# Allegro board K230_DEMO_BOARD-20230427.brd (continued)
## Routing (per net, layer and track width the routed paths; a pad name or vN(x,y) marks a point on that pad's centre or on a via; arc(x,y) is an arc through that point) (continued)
GND_SIGNAL: length 116.1
  TOP w0.254: U1.G8 U1.G7 v2(31.17,82.61)
  TOP w0.305: v1(64.77,133.22) TVS14.2 65.53,133.99 C156.2 ; TVS13.2 v1(62.99,136.27)
  TOP w0.381: C155.2 v1(61.34,133.48) ; v1(60.71,131.95) v1(56.45,127.7) v1(48.64,119.89) 48.64,108.08 v1(48.51,107.95) v1(44.07,103.5) v1(37.34,96.77) 31.11,90.55 v3(31.11,90.17) ; FB1.1 v1(60.33,134.75) ; J7.2 v1(74.4,130.66) ; C158.1 v1(65.91,131.32) ; v1(62.48,123.19) v1(56.52,123.19) 55.88,123.19 51.21,118.52 v1(51.21,114.83) 51.21,106.96 v1(49.66,105.41) v1(41.74,97.5) 35.2,90.96 35.2,90.07 v3(34.23,89.09) ; 74.3,118.24 v1(74.3,117.35) ; C160.1 v1(69.49,120.13)
  BOTTOM w0.254: C14.2 31.37,82.8 v2(31.17,82.61) ; 33.91,87.38 33.91,86.23
  BOTTOM w0.305: C238.2 41.71,97.54 v1(41.74,97.5)
  vias: v1(61.47,138.94) v1(64.26,138.94)
VDD_1V8: length 63.1
  TOP w0.203: v1(57.68,119.88) 58.11,119.45 U25.2 ; v2(42.52,111.23) 42.66,111.09 U30.C6 ; U30.P5 43.16,116.48 v2(42.93,116.71) ; v2(44.32,116.71) 44.32,116.44 U30.P3 U30.N4 U30.M4
  TOP w0.254: U1.R13 25.65,78.38 v2(25.33,78.06) ; U1.H6 v2(30.53,82.61) ; U1.R15 v2(25.33,77.41) ; U1.R11 v2(25.33,79.36) ; U1.F13 v2(31.17,78.06) ; v2(32.47,79.36) 32.15,79.68 U1.E11
  TOP w0.305: v1(57.3,115.06) R209.1 ; R143.1 14.61,44.07 ; R153.1 v1(40.64,16.26) ; R168.2 v1(29.21,26.04) ; v1(57.68,119.88) C207.1 ; R36.1 v1(31.75,26.04)
  TOP w0.381: R158.1 14.61,18.54 ; 72.26,38.73 v1(73.03,38.73) ; TP2.1 v1(13.84,15.88) ; R238.1 R239.1 v1(44.58,124.46) ; v1(51.31,82.93) 51.27,82.97 Y4.4 ; v1(45.72,124.46) R240.1 R241.1 ; R206.1 v1(7.11,40.64) ; R198.1 v1(7.11,48.26) ; J12.1 4.57,53.21 C206.2 ; R148.2 v1(20.7,26.16) ; R207.1 v1(7.11,38.1) ; 72.26,41.27 v1(73.03,41.27) ; R200.1 v1(7.11,43.18) ; R199.1 v1(7.11,45.72) ; J9.1 v1(32.7,119.89) ; R197.1 v1(7.11,50.8)
  ART06 w0.254: v2(31.17,78.06) v2(32.47,79.36)
  BOTTOM w0.254: v2(42.93,116.71) 43.18,116.46 C257.1 R49.2 v2(44.32,116.71) ; C258.1 41.15,111 R59.2 ; C258.1 42.29,111 v2(42.52,111.23) ; C258.1 42.04,109.98 C256.1
  BOTTOM w0.305: C10.1 v1(51.31,82.93) 48.64,82.93 47.24,81.53 40.77,81.53 39.75,80.52 38.99,80.52 38.99,79.5 ; v1(32.7,119.89) 32.7,120.21 C242.2 ; R236.1 R237.1 v1(5.71,82.51) ; R48.2 C259.1 v1(36.7,109.73)
  BOTTOM w0.381: v3(41.4,128.14) R234.1 R235.1
  vias: v1(15.24,46.99) v1(15.24,45.97) v1(15.24,44.07) v1(15.24,21.46) v1(15.24,20.45) v1(15.24,18.67) v1(15.24,17.65) v1(20.19,17.65) v1(20.19,16.64) v1(21.21,17.65) v1(21.21,16.64) v1(22.23,17.65) v1(22.23,16.64) v1(22.61,26.92) v1(22.61,25.91) v1(22.99,29.97) v1(22.99,28.96) v1(23.24,17.65) v1(23.24,16.64) v1(27.94,29.72) v1(27.94,28.83) v1(27.94,26.92) v1(27.94,25.91) v1(46.48,113.79) v1(47.37,113.79)
VDD_3V3: length 75.9
  TOP w0.203: U16.2 44.88,121.23 v1(44.32,121.79) ; U30.F5 42.82,112.28 v2(42.79,112.25) 42.66,112.12 U30.E6 ; v1(58.82,119.88) 58.51,119.57 U25.1 ; U30.K9 v2(41.16,113.8) 41.14,113.78 U30.J10
  TOP w0.254: U1.E10 v2(32.47,80.66) ; U1.M7 v2(27.28,82.61)
  TOP w0.305: J3.57 46.76,128.93 ; C272.2 v1(44.32,121.79) ; R156.1 v1(40.64,6.73) ; R139.1 35.94,27.56 ; J4.6 6.86,91.41 v1(6.6,91.15) 6.85,90.91 J4.5 ; v1(58.82,119.88) C208.2 ; J3.59 47.26,128.92
  TOP w0.381: v1(62.74,117.22) R243.1 R242.1 ; R19.1 19.3,8.89 ; R265.1 v1(59.69,23.68) ; R222.2 v1(15.62,10.79) ; v1(71.75,87) 67.06,87 66.86,87.19 U4.4 ; J9.16 v1(32.7,105.79) ; TP5.1 v1(13.59,9.91)
  BOTTOM w0.254: C18.1 41.15,113.82 v2(41.16,113.8) ; v2(32.47,80.66) 32.59,80.77 33.31,80.77
  BOTTOM w0.305: v2(42.79,112.25) 42.8,112.27 C22.1 C19.1 ; C81.1 C30.1 27.18,85.09 ; 35.81,80.14 C83.1 35.81,79.25 36.63,78.44 39.19,78.44 39.85,79.1 49.38,79.1 53.72,83.44 53.72,88.39 54.74,89.41 54.74,90.55 v1(58.42,94.23) ; R23.2 v1(43.43,117.47)
  BOTTOM w0.381: v1(32.7,105.79) 32.7,105.35 C260.1 ; R188.1 v1(70.99,85.09) ; R162.1 v1(70.99,87.63) ; R194.1 v1(70.99,83.19) R189.1 ; R245.2 v1(70.99,86.36) ; R191.1 v1(70.99,90.17) ; R190.1 v1(70.99,81.92) ; R193.1 v1(70.99,88.9)
  vias: v1(7.24,26.92) v1(7.24,25.65) v1(9.02,26.92) v1(9.02,25.65) v1(10.16,26.92) v1(10.16,25.65) v1(15.37,33.91) v1(15.37,32.89) v1(19.68,7.62) v1(19.68,6.48) v1(20.7,7.62) v1(20.7,6.48) v1(22.23,7.62) v1(22.23,6.48) v1(23.24,7.62) v1(23.24,6.48) v1(36.07,26.92) v1(36.07,25.91) v1(37.08,26.92) v1(37.08,25.91) v1(47.37,128.78) v1(48.39,128.78) v1(49.4,128.78) v1(50.55,128.78) v1(58.42,95.38) v1(59.82,98.17) v1(60.71,98.17) v2(38.1,114.43) v2(38.1,113.79)
VDD_5V: length 10.6
  TOP w0.254: U18.2 57.55,73.17
  TOP w0.305: U17.3 36.57,19.93 ; U20.3 51.05,49.15 ; R246.1 v1(19.56,26.16) ; U11.4 29.46,29.47 v1(29.59,29.34) 30.48,28.45 C164.1 ; U21.3 36.57,10.41 ; R151.1 v1(47.24,45.09)
  TOP w0.381: R172.1 56.9,79.63 v1(56.9,80.01) ; R186.1 42.93,28.83 ; R137.2 64.14,27.3
  vias: v1(37.08,20.83) v1(37.08,19.81) v1(37.08,11.3) v1(37.08,10.29) v1(38.35,19.81) v1(38.35,10.29) v1(39.62,19.81) v1(39.62,10.29) v1(50.93,48.64) v1(50.93,47.37) v1(50.93,46.1) v1(52.07,48.64) v1(53.98,25.53) v1(55.12,19.56) v1(55.12,18.29) v1(55.24,25.53) v1(55.24,24.26) v1(55.24,22.99) v1(55.24,21.72) v1(56.39,19.56) v1(56.39,18.29) v1(57.28,71.63) v1(57.28,70.36) v1(57.28,69.09) v1(57.28,67.82) v1(57.66,19.56) v1(57.66,18.29) v1(59.05,19.56) v1(59.05,18.29) v1(61.59,19.56) v1(61.59,18.29) v1(62.87,19.56) v1(62.87,18.29) v1(63.5,49.78) v1(64.14,19.56) v1(64.14,18.29) v1(64.77,49.78) v1(64.77,48.51) v1(64.77,47.24) v1(65.41,19.56) v1(65.41,18.29) v3(43.56,30.73) v3(43.56,29.72) v3(43.81,45.97) v3(43.81,44.96)
VDD_5V_O: length 24.5
  TOP w0.305: v1(57.53,85.47) 54.36,88.65 R43.2 R39.2 ; J4.4 8.88,90.41 ; J3.60 47.26,135.75 47.24,135.76 ; J3.58 46.76,135.75 ; J3.56 46.26,135.75 ; J4.3 8.88,89.91
  TOP w0.381: v1(66.55,67.5) U3.5 ; v1(66.55,57.34) U6.5
  BOTTOM w0.381: C16.2 66.61,67.56 v1(66.55,67.5) 65.85,67.5 ; 65.72,57.34 v1(66.55,57.34) 66.61,57.4 C20.2
  vias: v1(9.02,90.17) v1(9.02,89.15) v1(9.91,89.66) v1(40.64,137.41) v1(40.64,136.14) v1(41.91,137.41) v1(41.91,136.14) v1(62.48,31.24) v1(62.48,30.23) v1(64.52,31.24) v1(64.52,30.23) v1(67.69,31.24) v1(67.69,30.23)
VDD_CORE_0V8: length 92.9
  TOP w0.254: U1.K11 v2(29.22,80.01) ; v2(29.22,80.66) 28.9,80.98 U1.K9 ; U1.P9 v2(26.63,81.31) U1.N9 ; U1.M11 v2(27.93,79.36) ; U1.G10 v2(31.17,80.01) ; v2(30.53,80.66) 30.85,80.98 U1.G9 ; U1.F12 v2(31.17,78.71) ; U1.L11 v2(28.57,80.01) ; U1.L9 v2(27.93,81.31) U1.M9 ; U1.N11 v2(26.63,79.36) ; U1.P13 v2(25.98,78.71) ; U1.P11 v2(25.98,79.36)
  TOP w0.305: 41.4,78.36 41.4,78.11 41.78,77.72 41.78,76.96
  ART06 w0.305: v1(43.24,8.26) 43.24,28.01 40.26,30.99 40.26,47.24 47.5,54.48 47.5,60.96 v1(48.64,62.1)
  BOTTOM w0.254: C44.1 38.23,73.79 v2(37.72,73.28) ; C39.1 27.05,81.79 26.63,81.36 v2(26.63,81.31) ; C43.1 C36.1 C37.1 37.08,76.53 v2(36.5,77.11) ; v2(26.63,79.36) 26.48,79.5 C47.1 ; v2(39.62,81.41) 39.5,81.53 38.99,81.53 38.99,83.31 ; C38.1 28.32,81.79 27.93,81.39 v2(27.93,81.31)
  BOTTOM w0.305: v1(43.24,8.26) 31.75,8.26 27.94,4.45
  vias: v1(46.61,63.25) v1(46.61,62.1) v1(47.62,63.25) v1(48.64,64.64) v1(48.64,63.25) v1(50.04,64.64) v1(50.04,63.63) v1(51.44,64.64) v1(51.44,63.63) v1(51.44,62.61) v1(51.44,61.59) v2(40.39,80.37) v2(40.39,79.58) v2(40.39,78.61)
VDD_CORE_SY: length 80.5
  TOP w0.305: 47.62,57.15 47.62,48.9 C190.2 R174.2
  ART06 w0.305: v1(44.63,8.26) 44.63,27.76 41.53,30.86 41.53,47.62 48.13,54.23 48.13,58.29 v1(48.64,58.8)
  BOTTOM w0.305: v1(44.63,8.26) 43.87,7.49 33.53,7.49 30.48,4.45
VDD_CPU_0V8: length 41.1
  TOP w0.254: U1.J12 v2(29.87,78.71) ; U1.G12 v2(30.52,78.71) U1.H12
  ART06 w0.381: v1(50.8,37.47) 47.5,34.16 47.5,4.57 45.97,3.05 44.32,3.05 43.18,1.91
  vias: v1(51.82,40.77) v1(51.82,37.47) v1(52.83,40.77) v1(52.83,39.75) v1(52.83,38.48) v1(52.83,37.47) v1(53.85,40.77) v1(53.85,39.75) v1(54.86,40.77) v1(54.86,39.75) v1(56.01,40.77) v1(56.01,39.75) v1(56.01,38.48) v3(44.32,73.03) v3(45.09,73.03) v3(45.09,72.26)
VDD_CPU_TI: length 39
  TOP w0.254: 50.67,33.37 50.67,28.96 51.19,28.44 U28.8
  ART06 w0.381: v1(50.67,33.4) 50.04,32.77 50.04,20.57 48.13,18.67 48.13,4.32 45.72,1.91
VDD_IO1V8_SY: length 31
  TOP w0.305: R149.2 C170.2 28.96,17.02
  ART06 w0.254: v1(27.94,17.02) 27.94,13.72 36.83,4.83 36.83,3.68 37.34,3.17 39.37,3.17 40.64,1.91
VDD_IO3V3_SY: length 13.5
  TOP w0.305: 24.96,7.68 24.96,6.54 22.86,4.45 ; 28.96,7.49 C196.2 R169.2
VDD_KPU_0V8: length 95.8
  TOP w0.254: U1.H10 v2(29.87,80.66) U1.J10 ; U1.J9 v2(29.87,81.31) U1.H9 ; U1.H8 v2(29.87,81.96) U1.J8
  TOP w0.305: v1(68.58,13.08) 67.94,12.45 67.94,7.37 66.67,6.1 39.75,6.1 38.1,4.45
  ART06 w0.305: v1(68.58,13.08) 67.06,14.61 67.06,42.8 67.98,43.73 67.98,52.16 65.8,54.34 65.8,57.26 62.23,60.83 61.84,60.83 60.96,61.71 v1(60.96,62.14)
  BOTTOM w0.254: C53.1 C54.1 C55.1 v2(37.21,86.87)
  vias: v1(50.8,89.41) v1(52.58,89.41) v1(53.72,89.41) v1(55.63,89.41) v1(57.53,89.28) v1(57.53,88.01) v1(59.31,89.28) v1(59.31,88.01) v1(59.94,65.19) v1(59.94,64.17) v1(59.94,63.16) v1(60.33,89.28) v1(60.33,88.01) v1(60.96,65.19) v1(60.96,64.17) v1(60.96,63.16) v1(61.34,89.28) v1(61.34,88.01) v1(62.23,65.19) v1(62.23,64.17) v1(62.23,63.16) v1(62.23,62.14) v1(64.39,65.15) v2(41.02,84.98) v2(41.02,83.82)
VDD_KPU_TI: length 93.3
  TOP w0.254: U27.8 61.35,51.94 60.83,52.45 60.83,57.4
  TOP w0.305: v1(68.58,12.06) 68.58,7.24 66.93,5.59 41.78,5.59 40.64,4.45
  ART06 w0.305: v1(68.58,12.06) 68.58,12.19 66.55,14.22 66.55,43.18 67.5,44.13 67.5,51.93 66,53.43 61.14,53.43 60.83,53.73 v1(60.83,58.55)
3D_CTRL_IN: length 83.8
  TOP w0.127: R83.1 v1(6.22,77.34) ; J3.49 44.76,131.39 44.32,131.83 v3(43.94,131.83)
  ART06 w0.127: v3(43.94,131.83) 43.69,132.08 42.74,132.08 40.32,129.67 33.27,129.67 21.21,117.6 21.21,88.77 19.3,86.87 14.73,86.87 13.21,85.34 8.51,85.34 7.51,84.34 7.51,78.63 v1(6.22,77.34)
3D_CTRL_OUT1: length 89.3
  TOP w0.127: v3(42.82,131.6) 43,131.42 43.97,131.42 44.26,131.13 J3.47 ; R85.1 v1(6.22,70.48)
  ART06 w0.127: v1(6.22,70.48) 7.79,72.05 7.79,84.11 8.66,84.99 13.46,84.99 14.9,86.42 19.49,86.42 21.59,88.52 21.59,117.47 33.4,129.29 40.51,129.29 v3(42.82,131.6)
3D_CTRL_OUT2: length 89.5
  TOP w0.127: v1(2.41,80.14) 4.7,80.14 6.35,78.49 R87.1 ; v3(43.76,132.59) J3.46
  ART06 w0.127: v3(43.76,132.59) 43.25,133.1 32.44,133.1 18.03,118.69 18.03,92.96 15.49,90.42 12.05,90.42 9.89,88.27 6.22,88.27 4.45,86.49 3.56,86.49 1.02,83.95 1.02,81.53 v1(2.41,80.14)
ADC_0: length 58.1
  TOP w0.127: v1(53.72,103.89) 50.16,100.33 50.16,93.47 49.4,92.71 49.4,91.95 R25.1 ; R51.1 47.62,124.97 v1(47.62,123.32)
  ART06 w0.127: v1(53.72,103.89) 52.7,103.89 50.04,106.55 50.04,120.9 v1(47.62,123.32)
  BOTTOM w0.127: v1(47.62,123.32) 47.62,124.71 49.91,127 49.91,133.22 46.48,136.65 45.59,136.65 J15.1
ADC_1: length 51.8
  TOP w0.127: v1(52.66,104.73) 49.4,101.47 49.4,94.23 R26.1 ; v1(49.91,123.44) 49.91,124.97 R52.1
  ART06 w0.127: v1(52.66,104.73) 50.55,106.85 50.55,122.81 v1(49.91,123.44)
  BOTTOM w0.127: v1(49.91,123.44) 49.91,124.97 51.18,126.24 51.18,133.6 J15.2
ADC_2: length 59.7
  TOP w0.127: R27.1 49.78,91.19 49.78,92.33 50.55,93.09 50.55,99.82 54.23,103.5 54.23,106.3 53.09,107.44 v1(52.7,107.44) ; J3.52 45.26,132.62 46.3,131.57 v1(47.88,131.57) 49.53,133.22 J15.3
  ART06 w0.127: v1(47.88,131.57) 47.88,128.52 53.72,122.68 53.72,115.95 52.07,114.3 52.07,108.08 v1(52.7,107.44)
ADC_3: length 46.7
  TOP w0.127: R28.1 48.39,101.73 v1(52.66,106)
  ART06 w0.127: v1(52.66,106) 52.66,106.51 53.59,107.44 53.59,114.33 55.5,116.24 55.5,134.37 J15.4
ADC_4: length 49.8
  TOP w0.127: v1(53.68,104.86) 49.78,100.97 49.78,93.85 49.02,93.09 49.02,92.71 R29.1
  ART06 w0.127: J15.5 55.88,136.53 55.88,116.08 53.98,114.17 53.98,107.19 53.17,106.38 53.17,105.37 v1(53.68,104.86)
ADC_5: length 63.8
  TOP w0.127: 71.75,118.24 v1(71.75,117.35) ; v1(53.68,106) 53.04,105.37 52.54,105.37 49.02,101.85 49.02,95 R30.1
  ART06 w0.127: v1(71.75,117.35) 64.01,117.35 62.74,116.08 57.66,116.08 57.02,116.71 ; v1(53.68,106) 54.36,106.68 54.36,114.05 57.02,116.71 ; J15.6 57.15,136.78 57.02,136.65 57.02,116.71
BOOT0: length 77.2
  TOP w0.127: SW1.1 64.77,43.18 65.02,43.43 v1(70.87,43.43) TVS4.1 70.87,41.66 R18.1 ; U1.C8 v2(33.77,81.96)
  ART06 w0.127: v2(33.77,81.96) 36.75,81.96 36.96,82.17 41.27,82.17 42.29,81.15 47.5,81.15 50.55,78.11 52.45,78.11 55.5,75.06 55.5,71.63 56.13,70.99 58.93,70.99 63.82,66.1 63.82,62.55 65.41,60.96 68.83,60.96 70.1,59.69 70.1,56.9 71.5,55.5 71.5,44.07 v1(70.87,43.43)
BOOT1: length 80.9
  TOP w0.127: U1.C9 33.13,81.31 v2(33.12,81.31) ; SW1.2 62.23,40.51 62.74,40.01 v1(69.34,40.01) TVS5.1 70.87,39.12 R20.1
  ART06 w0.127: v2(33.12,81.31) 33.65,80.78 40.75,80.78 42.04,79.5 47.88,79.5 50.67,76.71 52.96,76.71 54.74,74.93 54.74,70.61 56.9,68.45 60.45,68.45 63.12,65.79 63.12,62.23 65.28,60.07 66.07,60.07 68.45,57.68 68.45,53.98 70.61,51.82 70.61,44.58 69.34,43.31 v1(69.34,40.01)
CC1: length 6.6
  TOP w0.127: J2.B5 73.45,15.7 73.91,15.24 v1(73.91,13.46) 73.91,13.08 73.53,12.7 J2.A5
  BOTTOM w0.127: R9.1 v1(73.91,13.46)
CC_T: length 13
  TOP w0.127: R195.1 68.45,109.22 69.53,108.15 69.53,106.5 70.11,105.91 J6.B5 73.29,105.91 74.17,105.03 74.17,103.76 73.32,102.91 J6.A5
DDR_1V8: length 50.1
  TOP w0.254: v2(23.05,51.34) 23.38,51.01 U5.A4 ; v2(23.7,52.94) 23.7,52.87 U5.A6 ; v2(23.7,49.74) 23.7,49.81 U5.A3 ; U5.U10 v2(34.42,55.74) ; v2(34.1,52.14) 34.1,52.22 U5.U6 ; U5.A10 v2(22.61,55.74) ; v2(34.1,49.74) 34.1,49.81 U5.U3 ; v2(34.1,51.34) 34.1,51.41 U5.U5 ; U5.U4 34.1,50.61 v2(34.1,50.54) ; U5.A5 23.38,51.81 v2(23.05,52.14)
  ART06 w0.305: J10.3 41.91,5.71 41.91,24 35.94,29.97 35.94,40.77 v1(35.81,40.89)
  BOTTOM w0.254: C121.1 23.47,52.7 v2(23.7,52.94) 23.7,54.65 v2(22.61,55.74) ; v2(23.7,49.74) 23.09,49.74
  vias: v1(21.21,49.78) v1(21.21,48.77) v1(34.67,42.04) v1(34.67,40.89) v1(35.81,42.04) v1(36.96,42.04) v1(36.96,40.89)
DDR_1V8_TI: length 34.3
  TOP w0.305: R138.2 35.94,35.18
  ART06 w0.305: J10.1 42.42,7.75 42.42,24.26 37.34,29.34 37.34,33.66 v1(36.7,34.29)
DDR_CORE_0V8: length 57
  TOP w0.254: U1.M13 v2(27.28,78.06) ; U1.L13 v2(28.58,78.71) U1.K13 ; U1.N13 v2(26.63,78.06)
  ART06 w0.254: v1(18.03,53.09) 16.51,53.09 11.94,48.51 11.94,38.61 11.43,38.1 11.43,8.26 15.24,4.45
  BOTTOM w0.254: C65.1 21.27,76.96 v2(21.06,76.75) 21.06,76.49 21.46,76.09 C66.1
  vias: v1(18.03,55.12) v1(18.03,54.08) v2(22.35,69.72) v2(22.35,68.95)
DDR_CORE_TI: length 50.2
  TOP w0.305: R177.1 14.61,51.44
  ART06 w0.305: 17.78,4.45 11.94,10.29 11.94,37.72 13.21,38.99 13.21,48.39 v1(14.99,50.16)
DDR_VAA_1V8: length 1.9
  TOP w0.254: U1.K15 v2(29.22,76.76)
  BOTTOM w0.254: C77.1 29.28,76.71 v2(29.22,76.76) ; C76.1 32.13,73.85 v2(31.82,74.16)
  vias: v1(38.35,42.04) v1(38.35,40.89) v1(39.5,42.04) v1(39.5,40.89) v1(40.89,42.04) v1(40.89,41.02)
DDR_VDD2_1V2: length 101.8
  TOP w0.203: v2(25.65,58.54) 26.06,58.13 26.06,57.43 25.98,57.34 U5.E12
  TOP w0.254: v2(32.15,50.54) 31.82,50.86 U5.P4 ; U5.E8 25.65,54.46 v2(25.65,54.54) ; v2(31.5,57.74) 31.5,57.67 U5.N12 ; U5.A11 v2(22.61,56.54) ; v2(27.6,51.34) 27.28,51.66 U5.G5 ; v2(26.95,48.94) 26.95,49.01 U5.G2 ; U5.A8 22.96,53.72 v2(22.48,53.72) ; U5.M2 30.85,49.01 v2(30.85,48.94) ; U1.L14 v2(27.93,77.41) ; v2(28.25,53.74) 28.25,53.81 U5.H8 ; U5.L12 29.87,57.42 v2(29.55,57.74) ; U5.U11 v2(34.38,56.54) ; v2(30.2,51.34) 30.2,51.41 U5.L5 ; U1.J14 v2(29.22,77.41) ; v2(27.6,49.74) 27.6,49.81 U5.H3 ; U5.H11 27.93,56.47 v2(28.25,56.14) ; U5.D5 25.33,51.81 v2(25,52.14) ; U5.U9 v2(34.42,54.94) ; U5.K12 29.22,57.27 v2(29.55,56.94) ; U1.H14 v2(29.87,77.41) ; v2(29.55,51.34) 29.55,51.41 U5.K5 ; v2(25,58.54) 24.51,58.05 24.51,57.5 U5.C12 ; U5.L2 30.2,49.01 v2(30.2,48.94) ; U5.U8 34.04,53.88 v2(34.04,53.34) ; U5.G12 27.28,57.42 v2(27.6,57.74) 27.93,57.42 U5.H12 ; U5.H9 27.6,54.62 v2(27.6,54.54) ; v2(28.25,52.14) 27.93,51.81 U5.H5 ; U5.J6 28.57,52.61 v2(28.9,52.94) ; U5.D4 25.33,51.01 v2(25,51.34) ; v2(32.8,57.74) 32.8,57.67 U5.R12 ; v2(27.28,77.41) U1.M14 ; U5.J5 28.57,51.81 v2(28.9,52.14) ; U5.A9 v2(22.61,54.94) ; v2(30.1,61.85) C91.2 R66.2 ; v2(30.85,53.74) 31.17,54.07 U5.N8 ; U5.J10 28.57,55.67 v2(28.25,55.34) ; v2(27.6,52.14) 27.6,52.22 U5.H6 ; v2(26.3,48.94) 26.3,49.01 U5.F2 ; v2(29.55,56.14) 29.22,56.47 U5.K11 ; v2(25.65,52.94) 25.65,52.86 U5.D6 ; U5.J9 28.25,54.62 v2(28.25,54.54) ; U5.P5 31.82,51.66 v2(32.15,51.34) ; v2(32.15,52.94) 32.15,52.86 U5.P6 ; v2(28.9,53.74) 29.22,54.07 U5.K8 ; v2(26.63,77.41) U1.N14 ; v2(29.55,52.14) 29.55,52.22 U5.K6
  TOP w0.381: C264.2 R68.1 28.96,43.81 v1(29.46,43.31) ; R144.1 v1(16.76,30.99)
  ART06 w0.254: 27.94,1.91 26.67,3.17 26.67,5.97 17.4,15.24 17.4,30.35 v1(16.76,30.99) 17.4,31.62 17.4,39.88 v1(19.81,42.29)
  BOTTOM w0.254: v2(31.18,74.16) 30.99,73.97 C62.2 R57.1 C71.1 ; C72.1 27.94,75.45 v2(27.93,75.46) ; C74.1 28.14,77.19 v2(27.93,77.41)
  BOTTOM w0.381: R131.1 R84.1 ; R84.1 v1(36.32,43.31) ; R84.1 R133.1 ; v1(21.46,43.31) R258.1 R260.1 ; v1(28.32,43.31) R72.1 R71.1 ; R80.1 v3(36.96,53.09) ; R141.1 R76.1 v1(26.04,43.31) ; v1(23.75,43.31) R256.1 R254.1 ; R74.1 v1(31.75,43.31) ; R129.1 R88.1 v1(34.04,43.31)
  vias: v1(18.8,47.88) v1(18.8,46.86) v1(19.81,41.02) v1(21.08,42.29) v1(21.08,41.02) v1(22.35,42.29) v1(23.62,42.29) v1(24.89,42.29) v1(26.16,42.29) v1(27.43,42.29) v1(28.7,42.29) v1(29.97,42.29) v1(31.24,42.29) v1(32.51,42.29) v3(32.84,68.96) v3(34.04,68.97)
DDR_VDDQ_TI: length 39.7
  TOP w0.381: R38.1 28.38,36.58
  ART06 w0.305: v1(27.94,34.54) 26.67,33.27 26.67,13.59 34.16,6.1 34.16,3.68 33.66,3.17 31.75,3.17 30.48,1.91
DDR_VREF: length 6.6
  TOP w0.203: U1.K17 v2(29.22,75.46)
  BOTTOM w0.254: R58.1 R57.2 30.24,72.28 30.24,73.27 C62.1 C261.2 C262.1 29.33,75.56 v2(29.22,75.46)
DEBUG_DM: length 10.6
  TOP w0.114: J6.A7 71.58,104.41 ; 71.58,104.41 71.34,104.17 71.34,103.72 71.65,103.41 J6.B7 ; 71.58,104.41 71.42,104.57 69.83,104.57 66.59,107.81 66.04,107.81 65.96,107.73 U26.7
DEBUG_DP: length 11.5
  TOP w0.114: U26.8 65.96,108.23 66.04,108.15 66.73,108.15 69.97,104.91 J6.B6 73.38,104.91 73.5,104.8 73.5,104.02 73.38,103.91 J6.A6
DL_M_CLK2: length 77.1
  TOP w0.127: v1(6.35,79.63) R116.2 ; v3(40.25,131.57) J3.31
  ART06 w0.127: v1(6.35,79.63) 6.72,80 6.72,84.73 8.14,86.16 10.68,86.16 12.66,88.14 19.18,88.14 20.32,89.28 20.32,117.98 32.89,130.56 39.24,130.56 v3(40.25,131.57)
DL_M_CLK3: length 94.5
  TOP w0.127: R118.2 6.5,69.34 4.85,70.99 3.56,70.99 3.17,71.37 3.17,78.23 1.65,79.76 v1(1.65,82.3) ; J3.35 41.26,131.59 v3(40.26,132.59)
  ART06 w0.127: v3(40.26,132.59) 39.88,132.59 39.37,132.08 32.14,132.08 18.67,118.61 18.67,92.84 15.75,89.92 12.27,89.92 10.11,87.76 6.48,87.76 4.7,85.98 3.81,85.98 1.65,83.82 v1(1.65,82.3)
DP_M_CLK1: length 83.1
  TOP w0.127: R89.1 6.22,76.2 5.59,76.83 5.59,77.98 v1(4.45,79.12) ; J3.26 v3(38.75,131.57)
  ART06 w0.127: v3(38.75,131.57) 32.35,131.57 19.3,118.53 19.3,89.92 18.54,89.15 12.23,89.15 10.25,87.17 6.65,87.17 5.26,85.78 5.26,83.87 4.45,83.06 v1(4.45,79.12)
DP_RST: length 5.8
  TOP w0.127: v3(43.31,135.12) 43.26,135.06 J3.44
  BOTTOM w0.127: R179.1 43.31,131.43 v3(43.31,135.12)
DP_STROBE: length 6.6
  TOP w0.127: J3.50 44.76,134.8 45.08,135.12 v3(45.71,135.12)
  BOTTOM w0.127: v3(45.71,135.12) 46.48,134.35 R181.1
DP_VSYNC: length 5.9
  TOP w0.127: J3.48 v3(44.26,135.12)
  BOTTOM w0.127: R180.1 44.83,131.18 44.83,134.54 v3(44.26,135.12)
EMMC_CLK: length 44.4
  TOP w0.127: U1.A5 37.99,83.59 v2(38.35,83.95)
  BOTTOM w0.127: R50.1 38.73,110.11 42.42,106.43 43.94,106.43 49.4,100.97 49.4,91.69 47.21,89.5 47.21,86.83 45.83,85.46 44.59,85.46 44.2,85.85 43.46,85.85 42.06,84.45 38.86,84.45 v2(38.35,83.95)
EMMC_CMD: length 50.7
  TOP w0.127: v2(43.16,114.81) U30.M5 ; U1.D6 v2(33.12,83.26)
  BOTTOM w0.076: v2(33.12,83.26) 33.45,83.58 34.03,83.58
  BOTTOM w0.127: v2(43.16,114.81) 42.65,115.32 42.29,115.32 42.16,115.19 42.16,113.66 41.66,113.16 37.85,113.16 37.47,112.78 R48.1 37.97,111.89 38.1,111.76 38.1,109.98 39.12,108.97 39.12,105.28 46.5,97.9 46.5,91.86 42.14,87.5 40.51,87.5 39.5,86.49 38.35,86.49 35.45,83.58 34.03,83.58
EMMC_D0: length 50.8
  TOP w0.127: U30.A3 44.16,109.13 44.32,108.97 44.32,107.7 39.62,103 v1(39.5,103) ; U1.D5 v2(33.12,83.91)
  BOTTOM w0.076: 34.03,84.23 33.45,84.23 v2(33.12,83.91)
  BOTTOM w0.127: 34.03,84.23 35.08,84.23 38.1,87.25 39.24,87.25 41.78,89.79 41.78,90 41.29,90.49 41.29,90.7 41.44,90.85 41.65,90.85 42.14,90.36 42.35,90.36 43.18,91.19 44.45,91.19 45.72,92.46 45.72,97.41 44.32,98.81 38.86,98.81 38.73,98.93 38.73,99.31 38.86,99.44 39.75,99.44 39.88,99.57 39.88,99.82 39.7,100 38.88,100 38.73,100.15 38.73,100.36 38.88,100.51 39.86,100.51 39.98,100.64 39.98,100.86 39.83,101.02 38.88,101.02 38.73,101.17 38.73,101.38 38.88,101.53 39.88,101.53 40.01,101.65 40.01,101.98 39.88,102.11 38.88,102.11 38.73,102.26 38.73,102.85 38.88,103 v1(39.5,103)
EMMC_D1: length 50.7
  TOP w0.127: v1(39.5,103.89) 39.75,103.89 43.18,107.31 43.18,108.2 43.66,108.68 U30.A4 ; U1.C5 v2(33.77,83.91)
  BOTTOM w0.127: v2(33.77,83.91) 35.27,83.91 38.23,86.87 39.37,86.87 42.44,89.94 42.65,89.94 43.14,89.45 43.35,89.45 43.5,89.6 43.5,89.81 43.01,90.3 43.01,90.51 43.31,90.81 44.7,90.81 46.1,92.2 46.1,97.66 44.39,99.38 42.79,99.38 42.64,99.53 42.64,100.94 42.49,101.09 42.28,101.09 42.13,100.94 42.13,99.53 41.98,99.38 41.65,99.38 41.5,99.53 41.5,102.11 41.38,102.23 41.12,102.23 41,102.11 41,99.53 40.85,99.38 40.58,99.38 40.39,99.57 40.39,103 v1(39.5,103.89)
EMMC_D2: length 50.8
  TOP w0.076: 35.05,83.91 34.42,83.91 U1.B5
  TOP w0.127: v1(41.4,106.55) 41.4,107.82 42.16,108.58 42.67,108.58 43.16,109.07 U30.A5 ; 35.05,83.91 37.68,83.91 38.73,84.96 v2(39.24,84.96)
  BOTTOM w0.127: v1(41.4,106.55) 41.4,106.17 41.66,105.92 43.69,105.92 48.13,101.47 48.13,101.17 48.28,101.02 48.62,101.02 48.77,100.87 48.77,100.66 48.62,100.51 48.28,100.51 48.13,100.37 48.13,100.16 48.28,100.01 48.75,100.01 48.9,99.86 48.9,99.65 48.75,99.5 48.28,99.5 48.13,99.36 48.13,99.14 48.28,99 48.75,99 48.9,98.85 48.9,98.64 48.75,98.49 48.28,98.49 48.13,98.34 48.13,98.13 48.28,97.98 48.75,97.98 48.9,97.83 48.9,97.62 48.75,97.47 48.28,97.47 48.13,97.32 48.13,97.11 48.28,96.96 48.75,96.96 48.9,96.82 48.9,96.6 48.75,96.46 48.28,96.46 48.13,96.31 48.13,96.1 48.28,95.95 48.75,95.95 48.9,95.8 48.9,95.59 48.75,95.44 48.28,95.44 48.13,95.29 48.13,91.34 45.83,89.04 45.83,88.83 46.33,88.33 46.33,88.12 46.19,87.97 45.98,87.97 45.47,88.47 45.26,88.47 42.77,85.98 42.15,85.98 42,85.83 42,85.11 41.85,84.96 41.64,84.96 41.49,85.11 41.49,85.83 41.34,85.98 41.02,85.98 40.01,84.96 v2(39.24,84.96)
EMMC_D3: length 50.6
  TOP w0.076: 44.91,109.47 44.91,110.03 U30.B2
  TOP w0.127: 44.91,109.47 44.91,109.27 45.09,109.09 45.09,105.92 v1(43.31,104.14) ; U1.C6 v2(33.77,83.26)
  BOTTOM w0.127: v1(43.31,104.14) 43.05,103.89 42.8,103.89 42.65,104.03 42.65,105.01 42.5,105.16 41.48,105.16 41.35,105.03 41.35,104.7 41.45,104.6 41.99,104.6 42.14,104.44 42.14,104.01 42.01,103.89 41.55,103.89 41.42,103.76 41.42,103.48 42.1,102.81 42.31,102.81 42.8,103.3 43.01,103.3 43.16,103.15 43.16,102.94 42.67,102.45 42.67,102.24 42.82,102.09 43.03,102.09 43.72,102.78 43.9,102.78 44.08,102.6 44.08,102.42 43.39,101.73 43.39,101.52 45.59,99.31 45.8,99.31 46.61,100.12 46.82,100.12 46.97,99.97 46.97,99.76 46.16,98.96 46.16,98.74 46.94,97.96 46.94,91.67 42.39,87.12 40.64,87.12 39.62,86.11 38.53,86.11 35.69,83.26 v2(33.77,83.26)
EMMC_D4: length 50.7
  TOP w0.076: U30.B3 44.41,110.03 44.41,109.47
  TOP w0.127: U1.D7 v2(33.12,82.61) ; 44.41,109.47 44.41,109.26 44.7,108.97 44.7,106.43 v1(43.31,105.03)
  BOTTOM w0.076: v2(33.12,82.61) 33.45,82.93 34.03,82.93
  BOTTOM w0.127: v1(43.31,105.03) 45.13,103.21 45.13,103 43.94,101.81 43.94,101.6 44.09,101.45 44.3,101.45 45.49,102.64 45.7,102.64 45.85,102.49 45.85,102.28 44.66,101.09 44.66,100.88 44.81,100.73 45.02,100.73 46.21,101.92 46.42,101.92 46.57,101.77 46.57,101.56 45.49,100.48 45.49,100.3 45.67,100.12 45.85,100.12 46.93,101.2 47.14,101.2 47.34,100.99 47.34,99.25 47.19,99.1 47.01,99.1 46.86,98.95 46.86,98.74 47.01,98.6 47.19,98.6 47.34,98.45 47.34,91.56 42.46,86.68 40.7,86.68 39.75,85.72 38.61,85.72 35.81,82.93 34.03,82.93
EMMC_D5: length 50.7
  TOP w0.076: 43.91,109.24 43.91,110.03 U30.B4
  TOP w0.127: v1(46.35,82.93) 46.24,82.82 39.26,82.82 38.79,82.35 35.61,82.35 35.55,82.29 U1.A7 ; v1(43.69,107.95) 43.91,108.17 43.91,109.24
  BOTTOM w0.127: v1(46.35,82.93) 46.48,82.93 48.3,84.75 48.3,88.68 50.67,91.06 50.67,102.74 50.5,102.91 50.29,102.91 50,102.62 49.78,102.62 49.64,102.76 49.64,102.97 49.93,103.27 49.93,103.48 49.78,103.63 49.57,103.63 49.28,103.33 49.07,103.33 48.92,103.48 48.92,103.69 49.21,103.99 49.21,104.2 49.07,104.35 48.86,104.35 48.56,104.05 48.35,104.05 48.2,104.2 48.2,104.41 48.5,104.71 48.5,104.92 48.35,105.07 48.14,105.07 47.84,104.77 47.63,104.77 47.48,104.92 47.48,105.13 47.78,105.43 47.78,105.64 45.47,107.95 44.49,107.95 44.34,108.1 44.34,108.56 44.2,108.71 43.99,108.71 43.84,108.56 43.84,108.1 v1(43.69,107.95)
EMMC_D6: length 50.6
  TOP w0.076: U1.B7 34.42,82.61 35.05,82.61 ; U30.B5 43.41,110.03 43.41,109.24
  TOP w0.127: v2(40.13,83.22) 39.15,83.22 38.54,82.61 35.05,82.61 ; v1(42.42,107.95) 43.41,108.94 43.41,109.24
  BOTTOM w0.127: v1(42.42,107.95) 42.93,107.44 44.32,107.44 44.72,107.05 44.93,107.05 45.16,107.28 45.37,107.28 45.52,107.13 45.52,106.92 45.29,106.69 45.29,106.48 45.44,106.33 45.65,106.33 45.88,106.56 46.09,106.56 46.24,106.41 46.24,106.2 46.01,105.97 46.01,105.76 46.15,105.61 46.36,105.61 46.6,105.84 46.81,105.84 46.96,105.7 46.96,105.49 46.72,105.25 46.72,105.04 50.29,101.47 50.29,91.19 47.99,88.89 47.99,84.95 46.48,83.44 45.81,83.44 45.66,83.29 45.66,83.08 45.51,82.93 45.3,82.93 45.16,83.08 45.16,83.54 45.01,83.69 44.8,83.69 44.65,83.54 44.65,83.08 44.5,82.93 43.27,82.93 43.12,83.08 43.12,83.29 42.97,83.44 42.67,83.44 42.29,83.06 40.3,83.06 v2(40.13,83.22)
EMMC_D7: length 50.8
  TOP w0.076: U30.B6 42.91,110.03 42.91,109.47
  TOP w0.127: 42.91,109.47 42.91,109.33 42.42,108.84 41.91,108.84 40.51,107.44 v1(40.51,106.55) ; U1.C7 v2(33.77,82.61)
  BOTTOM w0.127: v2(33.77,82.61) 33.83,82.66 36.05,82.66 36.23,82.84 36.44,82.84 36.7,82.58 36.91,82.58 37.06,82.73 37.06,82.94 36.8,83.2 36.8,83.41 38.76,85.37 39.9,85.37 40.89,86.36 42.65,86.36 47.75,91.47 47.75,101.35 43.56,105.54 41.25,105.54 41.13,105.66 41.13,105.81 41.02,105.92 40.77,105.92 40.64,105.79 40.64,104.8 40.51,104.68 40.21,104.68 40.08,104.8 40.08,105.69 39.52,106.25 39.52,108 39.65,108.13 39.98,108.13 40.13,107.98 40.13,106.68 40.26,106.55 v1(40.51,106.55)
EMMC_RST: length 53.1
  TOP w0.127: U30.K5 v2(43.67,114.28) ; U1.A6 38.32,82.94 v2(39.37,83.99)
  BOTTOM w0.127: v2(39.37,83.99) 39.62,83.73 39.62,82.93 40.22,82.33 46.65,82.33 48.81,84.49 48.81,88.43 51.44,91.06 51.44,102.74 44.96,109.22 44.96,112.99 v2(43.67,114.28) R49.1 C25.1
EMMC_STROBE: length 48.1
  TOP w0.076: U1.B6 34.42,83.26 34.92,83.26
  TOP w0.127: 34.92,83.26 38.17,83.26 38.73,83.82 38.73,84.07 39.12,84.45 39.64,84.45 v2(40.13,83.96)
  BOTTOM w0.127: v2(40.13,83.96) 40.67,83.43 42.02,83.43 42.9,84.3 45.57,84.3 45.83,84.57 46.72,84.57 47.71,85.56 47.71,89.12 49.91,91.31 49.91,101.22 44.07,107.06 42.55,107.06 40.01,109.6 R59.1 R47.1
FT_12MHZ_IN: length 8
  TOP w0.254: Y5.3 67.32,100.36 67.32,102 C201.1 67.25,102.7 67.25,104.48 66.5,105.23 U26.2
FT_12MHZ_OUT: length 7
  TOP w0.254: U26.3 66.64,105.73 67.75,104.62 67.75,102.71 C204.1 67.83,102.13 67.83,101.36 Y5.1
FTVCC_1V8: length 9.7
  TOP w0.254: v1(64.02,102.38) 64.46,102.83 U26.64 ; U26.49 56.96,103.2 v1(56.52,102.76) ; U26.12 66.15,110.23 v1(66.43,110.51) ; U26.37 v1(55.13,110.23)
  BOTTOM w0.305: v1(55.13,110.23) 55.28,110.38 C221.2 ; C220.2 C202.2 56.65,102.89 v1(56.52,102.76) ; C222.2 63.51,102.89 ; C199.2 v1(66.43,110.51)
FTVCC_3V3: length 43.3
  TOP w0.203: U16.1 45.28,121.61 v1(45.47,121.79)
  TOP w0.254: U26.50 57.46,103.04 v1(57.74,102.76) ; U26.56 v1(60.46,102.77) ; U26.20 62.96,113.85 v1(62.62,114.19) ; U26.31 v1(57.46,113.91) ; U26.42 v1(55.13,107.73)
  TOP w0.305: R201.1 v1(68.45,112.65) ; C271.1 v1(45.47,121.79)
  TOP w0.381: v1(61.6,98.83) R205.1 R204.1 R203.1
  ART06 w0.381: v1(45.47,121.79) 49.53,117.73 49.53,106.43 52.7,103.25 55.88,103.25
  BOTTOM w0.305: C200.2 57.54,113.84 v1(57.46,113.91) ; C203.2 v1(62.62,114.19) ; v1(55.13,107.73) 55.24,107.84 C219.2 ; v1(57.74,102.76) 57.54,102.97 C217.2 C216.2 ; v1(60.46,102.77) 60.46,102.77 C218.2
  BOTTOM w0.381: FB7.1 v1(68.46,104.27) ; FB8.1 v1(68.46,108.2)
  vias: v1(58.81,101.49) v1(60.21,101.49)
GPIO9: length 1.8
  TOP w0.127: R184.2 v1(9.02,81.92)
  BOTTOM w0.127: R184.2 v1(9.02,81.92)
GPIO26: length 6.2
  TOP w0.127: R91.1 5.97,30.35 3.05,30.35 J8.1
GPIO27: length 131.5
  TOP w0.127: J3.36 41.26,131.97 v3(41.66,131.57) ; R93.1 v1(6.22,73.91)
  ART06 w0.127: v3(41.66,131.57) 40.13,130.05 33.15,130.05 20.83,117.73 20.83,88.9 19.18,87.25 14.5,87.25 12.9,85.65 8.36,85.65 7.23,84.52 7.23,79.24 5.73,77.74 5.73,76.82 6.73,75.82 6.73,74.42 v1(6.22,73.91) 5.73,73.42 5.73,54.5 5.08,53.85 5.08,29.84 J8.2
GPIO28: length 135.9
  TOP w0.127: R95.1 v1(6.22,75.06) ; J3.42 42.76,132.67 v3(42.67,132.59)
  ART06 w0.127: v3(42.67,132.59) 42.16,132.08 40.13,132.08 39.12,131.06 32.64,131.06 19.81,118.24 19.81,89.66 18.8,88.65 12.45,88.65 10.46,86.66 7.92,86.66 6.21,84.95 6.21,81.01 5.42,80.23 5.42,75.86 v1(6.22,75.06) 5.44,74.27 5.44,54.66 4.7,53.92 4.7,47.75 3.05,46.1 3.05,27.81 1.91,26.67
GPIO29: length 61.2
  TOP w0.127: R182.2 v1(8.89,84.45)
  ART06 w0.127: J8.4 5.46,27.69 5.46,53.75 6.4,54.69 6.4,69.85 8.08,71.53 8.08,83.64 v1(8.89,84.45)
  BOTTOM w0.127: R182.2 v1(8.89,84.45)
GPIO30: length 64.6
  TOP w0.127: R183.2 v1(8.89,83.19)
  ART06 w0.127: 1.91,24.13 3.17,25.4 5.08,25.4 5.84,26.16 5.84,53.72 6.68,54.56 6.68,69.72 8.38,71.42 8.38,82.68 v1(8.89,83.19)
  BOTTOM w0.127: R183.2 v1(8.89,83.19)
GPIO31: length 62.5
  TOP w0.127: R208.2 v1(8.89,80.77)
  ART06 w0.127: J8.8 6.22,23.37 6.22,53.59 6.96,54.33 6.96,69.57 8.79,71.4 8.79,80.67 v1(8.89,80.77)
  BOTTOM w0.127: R208.2 v1(8.89,80.77)
GPIO32: length 2.7
  TOP w0.127: R103.1 J8.6
GPIO33: length 6.2
  TOP w0.127: 1.91,21.59 3.05,22.73 5.97,22.73 R105.1
GPIO34: length 6.3
  TOP w0.127: 1.91,19.05 3.17,20.32 5.84,20.32 R107.1
GPIO35: length 6.2
  TOP w0.127: 1.91,16.51 3.05,17.65 5.97,17.65 R109.1
GPIO36: length 6.2
  TOP w0.127: 1.91,13.97 3.05,15.11 5.97,15.11 R111.1
GPIO37: length 6.2
  TOP w0.127: R113.1 6.99,11.56 6.99,11.68 6.1,12.57 3.05,12.57 1.91,11.43
GPIO42: length 36.6
  TOP w0.127: v1(36.83,104.14) 36.83,100.08 R100.2
  ART06 w0.127: v3(47.37,127.8) 46.57,127 45.59,127 37.21,118.62 37.21,104.52 v1(36.83,104.14)
  BOTTOM w0.127: v3(47.37,127.8) 46.86,128.31 46.86,129.41 R181.2
GPIO43: length 77.8
  TOP w0.127: R102.2 v1(49.28,84.07) ; v1(56.01,71.88) 56.01,68.71 R232.2
  ART06 w0.127: v3(49.4,127.8) 54.1,123.1 54.1,115.57 53.21,114.68 53.21,108.97 v1(52.7,108.46) ; v1(49.28,84.07) 55.12,84.07 56.26,82.93 56.26,79.88 55.88,79.5 55.88,72.01 v1(56.01,71.88)
  BOTTOM w0.127: v1(52.7,108.46) 51.94,107.7 51.94,96.39 52.7,95.63 52.7,93.6 52.07,92.96 52.07,89.79 50.04,87.76 50.04,84.84 v1(49.28,84.07) ; R180.2 45.21,129.16 47.12,127.25 48.86,127.25 v3(49.4,127.8)
GPIO46: length 36.4
  ART06 w0.127: v1(44.58,123.44) 42.55,123.44 37.59,118.49 37.59,104.78 v1(38.1,104.27)
  BOTTOM w0.127: v1(38.1,104.27) 36.83,103 R108.2 ; R179.2 45.09,128.64 45.09,123.95 v1(44.58,123.44)
GPIO47: length 46.4
  TOP w0.127: v3(39.37,135.25) 39.75,134.87 J3.30
  ART06 w0.127: v1(34.92,109.73) 34.92,117.98 44.45,127.51 44.45,132.59 43.56,133.48 41.15,133.48 v3(39.37,135.25)
  BOTTOM w0.127: v1(34.92,109.73) 33.27,108.08 33.27,99.95 R110.2
GPIO48: length 46.5
  TOP w0.127: J3.32 40.25,134.94 v3(40.13,135.06)
  ART06 w0.127: v3(40.13,135.06) 41.4,133.79 43.88,133.79 44.83,132.84 44.83,127.25 35.56,117.98 35.56,107.19 v1(36.32,106.43)
  BOTTOM w0.127: R112.2 34.16,99.31 34.16,105.16 35.43,106.43 v1(36.32,106.43)
GPIO49: length 45.6
  TOP w0.127: v3(40.89,135.06) 40.88,135.06 40.76,134.93 J3.34
  ART06 w0.127: v1(36.32,107.44) 36.07,107.7 36.07,117.98 45.21,127.13 45.21,132.97 44.07,134.11 41.84,134.11 v3(40.89,135.06)
  BOTTOM w0.127: R114.2 37.97,103 38.73,103.76 38.73,105.03 v1(36.32,107.44)
GPIO52: length 89.6
  TOP w0.127: v1(27.94,114.3) 29.09,114.3 31.88,117.09 41.4,117.09 43.72,119.42 U16.6
  ART06 w0.127: v1(26.42,102.62) 25.4,103.63 25.4,113.54 26.16,114.3 v1(27.94,114.3)
  BOTTOM w0.127: J5.2 J5.4 5.45,73.92 5.45,71.38 5.84,70.99 10.67,70.99 19.37,79.69 19.37,98.74 23.24,102.62 v1(26.42,102.62) 29.46,99.57 29.46,99.44 R119.1
GPIO53: length 144.8
  TOP w0.127: U16.5 43.36,119.82 v1(42.55,119) 41.02,117.47 31.34,117.47 29.18,115.32 v1(27.94,115.32)
  ART06 w0.127: v1(74.42,84.45) 72.39,86.49 72.39,90.55 67.82,95.12 66.17,95.12 64.39,96.9 60.96,96.9 60.2,97.66 57.91,97.66 55.31,100.27 53.91,100.27 49.02,105.16 49.02,116.46 46.48,119 v1(42.55,119) ; v1(27.94,115.32) 26.48,115.32 25.02,113.86 25.02,103 v1(26.42,101.6)
  BOTTOM w0.127: J5.6 4.45,71.25 5.84,69.85 10.03,69.85 19.81,79.63 19.81,98.42 22.99,101.6 v1(26.42,101.6) 28.57,99.44 28.57,99.19 R120.1 ; R55.2 R194.2 73.55,83.58 TVS12.1 v1(74.42,84.45)
GPIO60_3V3: length 60.9
  TOP w0.127: U25.12 v1(60.45,118.83) 61,119.38 R242.2
  ART06 w0.127: v1(24.26,99.82) 23.5,100.58 23.5,114.94 v1(27.94,119.38)
  BOTTOM w0.127: v1(27.94,119.38) 27.94,119.38 39.5,119.38 42.93,122.81 52.7,122.81 56.68,118.83 v1(60.45,118.83) ; R127.1 v1(24.26,99.82)
GPIO61_3V3: length 62
  TOP w0.127: R243.2 v1(60.99,117.37) 59.93,118.43 U25.11
  ART06 w0.127: v1(25.4,99.82) 23.88,101.35 23.88,114.68 27.56,118.37 v1(27.94,118.37)
  BOTTOM w0.127: v1(25.4,99.82) R128.1 ; v1(27.94,118.37) 28.57,119 39.75,119 43.18,122.43 52.45,122.43 57.51,117.37 v1(60.99,117.37)
HP_INSERT_DET: length 6.6
  TOP w0.127: R221.2 R35.2 C162.1 76.2,121.15 J7.6
HPOUTL: length 67.9
  TOP w0.127: v1(65.15,127.03) 57.3,127.03 49.53,119.25 49.53,107.57 30.85,88.89 U1.G1 ; C159.1 v1(65.15,120.4)
  ART03 w0.127: v1(65.15,120.4) v1(65.15,127.03)
HPOUTR: length 73.6
  TOP w0.076: U1.G2 31.18,85.86 31.18,86.47
  TOP w0.127: 31.18,86.47 31.18,88.81 49.91,107.54 49.91,119 56.64,125.73 v1(66.17,125.73) ; C161.1 67.94,135.38 v1(67.69,135.64)
  ART03 w0.127: v1(67.69,135.64) 68.96,134.37 68.96,128.52 v1(66.17,125.73)
HSY0: length 6.5
  TOP w0.127: J3.51 45.26,128.48 46.74,127 47.37,127 R51.2 R53.1
I2C0_SCL_1V8: length 32.1
  TOP w0.127: v1(54.61,119.38) 55.16,118.83 U25.3 ; J3.38 41.76,134.96 v3(41.66,135.06)
  ART06 w0.127: v1(54.61,119.38) 54.61,125.6 45.81,134.4 42.31,134.4 v3(41.66,135.06)
  BOTTOM w0.127: v3(41.66,135.06) 40.89,134.3 40.89,131.31 R234.2
I2C0_SDA_1V8: length 32.7
  TOP w0.127: J3.40 42.26,134.95 v3(42.42,135.12) ; U25.4 v1(54.67,118.43)
  ART06 w0.127: v3(42.42,135.12) 42.81,134.72 46,134.72 55.12,125.6 55.12,118.88 v1(54.67,118.43)
  BOTTOM w0.127: v3(42.42,135.12) 42.16,134.86 42.16,131.31 R235.2
I2C1_SCL: length 127.7
  TOP w0.127: R96.2 35.81,100.2 v1(35.81,104.2) ; v1(72.52,48.9) R219.1 ; R240.2 43.81,128.27 v1(43.43,128.27) 43.26,128.45 J3.43
  ART06 w0.127: v1(72.52,48.9) 72.52,55.5 71.63,56.39 71.63,68.96 69.85,70.74 69.85,90.93 67.31,93.47 63.12,93.47 62.23,94.36 61.21,94.36 58.42,97.16 52.83,97.16 48.01,101.98 38.03,101.98 v1(35.81,104.2) 33.66,106.36 33.66,119.13 42.55,128.02 43.18,128.02 v1(43.43,128.27)
I2C1_SDA: length 130.7
  TOP w0.127: J3.45 43.76,129.09 v1(43.94,128.91) 44.32,128.91 R241.2 ; v1(34.67,104.2) 34.67,100.2 R98.2 ; v1(72.39,47.62) R217.1
  ART06 w0.127: v1(72.39,47.62) 72.01,48.01 72.01,55.5 70.48,57.02 70.48,69.47 69.47,70.48 69.47,90.68 67.06,93.09 62.99,93.09 62.1,93.98 61.09,93.98 58.29,96.77 52.7,96.77 47.88,101.6 37.27,101.6 v1(34.67,104.2) 33.27,105.6 33.27,119.25 42.42,128.4 42.93,128.4 43.43,128.91 v1(43.94,128.91)
I2C3_SCL: length 38.3
  TOP w0.127: R104.2 37.34,99.44 37.34,104.39 v1(36.32,105.41) ; R239.2 v1(43.56,127.38) 42.76,128.19 J3.41
  ART06 w0.127: v1(43.56,127.38) 34.42,118.24 34.42,107.31 v1(36.32,105.41)
I2C3_SDA: length 36.9
  TOP w0.127: J3.39 42.26,127.54 v1(42.55,127.25) R238.2
  ART06 w0.127: v1(35.31,105.41) 34.04,106.68 34.04,118.75 v1(42.55,127.25)
  BOTTOM w0.127: R106.2 35.31,99.31 v1(35.31,105.41)
I2C4_SCL: length 131.3
  TOP w0.127: v1(3.81,85.09) 3.05,85.85 3.05,89.66 5.8,92.41 J4.8 ; R77.1 v1(6.22,72.77) ; R233.1 v1(57.02,30.48) ; v1(13.97,42.8) 12.95,42.8 11.68,44.07 11.68,50.04 5.46,56.26 v3(3.43,56.26)
  ART06 w0.127: v1(3.81,85.09) 4.32,84.58 4.32,83.95 3.43,83.06 v3(3.43,56.26) ; v1(42.16,39.75) 42.93,38.99 47.75,38.99 47.77,39 56.31,39 57.52,37.79 57.52,30.98 v1(57.02,30.48)
  BOTTOM w0.127: v1(6.22,72.77) 6.73,73.28 6.73,77.85 3.17,81.41 3.17,84.45 v1(3.81,85.09) 4.45,84.45 R236.2 ; v1(13.97,42.8) 14.61,42.16 14.61,41.53 16.76,39.37 41.78,39.37 v1(42.16,39.75)
I2C4_SDA: length 131.8
  TOP w0.127: v1(13.97,41.78) 13.34,41.78 11.18,43.94 11.18,49.91 5.84,55.24 v3(3.43,55.24) ; R79.1 v1(6.22,71.63) ; J4.9 5.81,92.91 2.67,89.77 2.67,85.34 v1(3.81,84.2) ; R220.1 57.91,28.83 57.91,30.61 v1(57.02,31.5)
  ART06 w0.127: v3(3.43,55.24) 2.92,55.75 2.92,83.31 v1(3.81,84.2) ; v1(57.02,31.5) 57.02,36.83 55.88,37.97 42.67,37.97 v1(42.16,38.48)
  BOTTOM w0.127: v1(6.22,71.63) 7.11,72.52 7.11,77.98 4.7,80.39 R237.2 4.7,83.31 v1(3.81,84.2) ; v1(13.97,41.78) 13.97,41.53 16.51,38.99 41.66,38.99 v1(42.16,38.48)
JTAG_RST: length 56.1
  TOP w0.127: U1.V14 v2(24.03,77.41) ; 1.91,40.64 R206.2 5.21,41.27 5.46,41.53 v1(10.54,41.53)
  ART06 w0.127: v2(24.03,77.41) 17.63,77.41 12.83,72.61 12.83,71.37 9.78,68.33 9.78,56.08 11.01,54.85 11.01,42 v1(10.54,41.53)
JTAG_TCK: length 40.9
  TOP w0.076: U1.W15 22.73,76.76 22.16,76.76
  TOP w0.127: v3(4.01,57.15) 5.59,57.15 6.48,58.04 6.48,63.37 19.47,76.37 21.17,76.37 21.57,76.76 22.16,76.76 ; R197.2 J12.3
  ART06 w0.127: v3(4.01,57.15) 4.01,54.85 3.43,54.27 3.43,52.32 J12.3
JTAG_TDI: length 46.8
  TOP w0.076: 22.04,77.41 23.38,77.41 U1.V15
  TOP w0.127: v3(4.99,58.17) 5.59,58.76 5.59,63.78 19.21,77.41 22.04,77.41 ; 1.91,45.72 R199.2
  ART06 w0.127: v3(4.99,58.17) 4.99,54.65 4.32,53.98 4.32,48.13 1.91,45.72
JTAG_TDO: length 44.3
  TOP w0.127: U1.Y15 19.35,77.09 5.97,63.71 5.97,58.29 5.33,57.66 4.52,57.66 v3(4.01,58.17) ; R198.2 J12.4
  ART06 w0.127: J12.4 3.94,50.29 3.94,54.05 4.56,54.67 4.56,57.62 v3(4.01,58.17)
JTAG_TMS: length 55.7
  TOP w0.127: v1(10.41,44.07) 5.59,44.07 5.21,43.69 R200.2 1.91,43.18 ; U1.U14 v2(24.03,78.06)
  ART06 w0.076: v2(24.03,78.06) 23.7,78.39 23.11,78.39
  ART06 w0.127: v1(10.41,44.07) 10.41,54.61 9.25,55.78 9.25,68.53 12.32,71.6 12.32,72.82 14.73,75.23 14.73,77.22 15.94,78.42 17.08,78.42 17.4,78.74 22.1,78.74 22.45,78.39 23.11,78.39
LCD_EN: length 32.2
  TOP w0.127: J4.29 3.09,102.91 0.83,100.65 0.83,84.14 4.19,80.77 R208.1
LCD_RST: length 30.2
  TOP w0.127: J4.28 3.35,102.41 1.33,100.39 1.33,84.39 3.81,81.92 R184.1
LP3_CA0: length 49.6
  TOP w0.076: v2(32.15,48.94) 32.47,49.26 U5.R2 ; R86.2 v1(36.32,46.23) ; U1.K20 v2(29.22,73.51)
  ART03 w0.076: v2(32.15,48.94) 31.82,49.26 31.82,51.36 31.7,51.49 31.27,51.49 31.17,51.58 31.17,58.85 31.25,58.93 34.2,58.93 34.33,58.79 34.33,58.58 34.47,58.45 34.66,58.45 34.79,58.58 34.79,58.84 34.92,58.98 35.11,58.98 35.25,58.84 35.25,58.58 35.38,58.45 35.57,58.45 35.71,58.58 35.71,58.79 35.92,59 35.92,64.28 35.78,64.41 34.93,64.41 34.8,64.55 34.8,64.73 34.93,64.87 35.78,64.87 35.92,65 35.92,65.38 35.79,65.51 34.53,65.51 34.4,65.37 34.4,65.06 34.27,64.92 34.08,64.92 33.94,65.06 33.94,65.37 33.81,65.51 32.59,65.51 32.38,65.71 32.38,69.74 32.26,69.87 31.17,69.87 31.04,69.99 31.04,70.2 31.17,70.32 32.26,70.32 32.38,70.45 32.38,70.73 29.6,73.51 v2(29.22,73.51)
  ART06 w0.076: v2(32.15,48.94) 33.08,48.01 34.54,48.01 v1(36.32,46.23)
  BOTTOM w0.076: R86.2 v1(36.32,46.23)
LP3_CA1: length 48.1
  TOP w0.076: v2(31.5,48.94) 31.82,49.26 U5.P2 ; U1.L20 v2(28.57,73.51) ; R90.2 v1(34.04,46.23)
  ART03 w0.076: v2(31.5,48.94) 31.17,49.26 31.17,50.04 31.07,50.14 30.76,50.14 30.53,50.37 30.53,50.67 30.25,50.95 30.05,50.95 29.87,51.13 29.87,58.6 30.05,58.77 30.05,59.08 29.87,59.25 29.87,59.47 30.05,59.64 33.69,59.64 33.77,59.72 33.77,61.49 33.85,61.57 35.18,61.57 35.26,61.65 35.26,61.96 35.15,62.06 34.54,62.06 34.44,62.16 34.44,62.44 34.52,62.52 35.16,62.52 35.26,62.61 35.26,62.99 35.18,63.07 32.64,63.07 32.54,63.17 32.54,63.38 32.67,63.52 33.01,63.52 33.15,63.65 33.15,63.84 33.01,63.97 32.67,63.97 32.54,64.11 32.54,64.69 32.4,64.82 32.21,64.82 32.08,64.69 32.08,63.2 31.95,63.07 31.76,63.07 31.62,63.2 31.62,68.15 30.1,69.67 30.1,71.37 28.88,72.59 28.88,73.21 v2(28.57,73.51)
  ART06 w0.076: v1(34.04,46.23) 33.15,47.12 32.89,47.12 31.5,48.51 v2(31.5,48.94)
  BOTTOM w0.076: R90.2 v1(34.04,46.23)
LP3_CA2: length 49.4
  TOP w0.076: v2(28.56,72.81) 28.33,72.81 27.66,73.48 27.66,73.77 U1.M20 ; v2(30.85,49.74) 31.17,49.41 U5.N2 ; R130.2 v1(32.89,46.23)
  ART03 w0.076: v2(30.85,49.74) 30.68,49.74 30.25,50.16 30.12,50.16 29.22,51.06 29.22,59.88 29.31,59.97 33.38,59.97 33.5,60.1 33.5,60.36 33.38,60.49 31.36,60.49 31.24,60.6 31.24,60.88 31.37,61.01 33.36,61.01 33.44,61.09 33.44,61.35 33.32,61.47 31.37,61.47 31.24,61.6 31.24,62.11 31.37,62.23 34.01,62.23 34.11,62.34 34.11,62.59 34.01,62.69 31.37,62.69 31.24,62.82 31.24,68.05 29.72,69.57 29.72,71.25 28.56,72.4 v2(28.56,72.81)
  ART06 w0.076: v1(32.89,46.23) 32.89,46.61 31.17,48.33 31.17,49.41 v2(30.85,49.74)
  BOTTOM w0.076: R130.2 v1(32.89,46.23)
LP3_CA3: length 53.6
  TOP w0.076: v1(37.47,46.23) R132.2 ; v2(32.15,49.74) 31.57,49.74 U5.N3 ; U1.L17 v2(28.57,75.46)
  ART03 w0.076: v2(32.15,49.74) 33.12,50.71 33.12,57.51 33.27,57.66 33.56,57.66 33.69,57.52 33.69,57.08 33.83,56.95 34.02,56.95 34.15,57.08 34.15,57.52 34.28,57.66 36.42,57.66 36.58,57.81 36.58,66.09 36.5,66.17 34.09,66.17 33.96,66.29 33.96,66.52 34.09,66.65 36.47,66.65 36.58,66.75 36.58,67 36.47,67.11 34.47,67.11 34.37,67.21 34.37,67.46 34.47,67.56 35.92,67.56 36.02,67.67 36.02,67.92 35.92,68.02 34.65,68.02 34.52,68.15 34.52,69.53 29.57,74.49 29.08,74.49 28.9,74.67 28.9,75.14 v2(28.57,75.46)
  ART06 w0.076: v1(37.47,46.23) 34.37,49.33 32.56,49.33 v2(32.15,49.74)
  BOTTOM w0.076: R132.2 v1(37.47,46.23)
LP3_CA4: length 51.3
  TOP w0.076: v2(30.85,50.54) 30.52,50.21 U5.M3 ; U1.M19 27.93,74.16 27.93,73.7 28.47,73.15 29.49,73.15 v2(29.83,72.81) ; R134.2 v1(35.18,46.23)
  ART03 w0.076: v2(29.83,72.81) 29.83,72.25 30.52,71.56 30.52,69.75 31.13,69.14 31.32,69.14 31.67,69.49 31.86,69.49 31.99,69.35 31.99,69.16 31.65,68.82 31.65,68.63 32,68.28 32,65.25 32.09,65.16 33.39,65.16 33.53,65.03 33.53,63.58 33.68,63.42 33.91,63.42 34.05,63.56 34.05,63.87 34.18,64.01 34.37,64.01 34.5,63.87 34.5,63.53 34.61,63.42 34.92,63.42 35,63.5 35,63.86 35.13,63.98 35.46,63.98 35.59,63.86 35.59,61.38 35.38,61.17 34.25,61.17 34.11,61.04 34.11,60.82 34.24,60.69 35.38,60.69 35.51,60.57 35.51,60.36 35.38,60.24 34.32,60.24 34.19,60.11 34.19,59.89 34.32,59.77 35.28,59.77 35.41,59.64 35.41,59.41 35.31,59.31 30.89,59.31 30.73,59.16 30.73,57.4 30.52,57.19 30.52,51.14 30.85,50.81 v2(30.85,50.54)
  ART06 w0.076: v1(35.18,46.23) 33.78,47.62 33.02,47.62 31.82,48.82 31.82,49.56 v2(30.85,50.54)
  BOTTOM w0.076: R134.2 v1(35.18,46.23)
LP3_CA5: length 52.2
  TOP w0.076: v2(26.95,50.54) 26.63,50.21 U5.F3 ; R253.2 v1(24.89,46.23) ; U1.L16 v2(27.93,76.11)
  ART03 w0.076: v2(26.95,50.54) 27.28,50.86 27.28,56.39 27.4,56.52 28.27,56.52 28.45,56.69 28.45,57.05 28.35,57.15 28,57.15 27.86,57.28 27.86,57.47 28,57.61 28.35,57.61 28.45,57.71 28.45,63.74 28.58,63.87 30.4,63.87 30.53,64.01 30.53,64.2 30.4,64.33 28.56,64.33 28.45,64.44 28.45,64.69 28.54,64.79 30.4,64.79 30.53,64.92 30.53,65.11 30.4,65.25 28.58,65.25 28.45,65.38 28.45,65.63 28.55,65.74 30.4,65.74 30.53,65.86 30.53,66.06 30.4,66.19 28.79,66.19 28.65,66.32 28.65,66.51 28.79,66.65 30.37,66.65 30.51,66.78 30.51,67.67 30.3,67.87 28.98,67.87 28.88,67.97 28.88,68.21 29.01,68.34 29.43,68.34 29.57,68.48 29.57,68.66 29.43,68.8 29.01,68.8 28.88,68.93 28.88,71.07 27.94,72.01 27.94,73.91 27.6,74.25 27.6,76.03 27.68,76.11 v2(27.93,76.11)
  ART06 w0.076: v1(24.89,46.23) 24.89,46.99 26.63,48.72 26.63,50.21 v2(26.95,50.54)
  BOTTOM w0.076: R253.2 v1(24.89,46.23)
LP3_CA6: length 50.8
  TOP w0.076: v2(26.3,50.54) 26.3,50.46 U5.E3 ; U1.N19 v2(27.28,74.16) ; R255.2 v1(22.61,46.23)
  ART03 w0.076: v2(27.28,74.16) 27.62,73.81 27.62,71.69 28.45,70.87 28.45,67.69 28.6,67.54 30.07,67.54 30.18,67.44 30.18,67.18 30.02,67.03 27.43,67.03 27.33,66.93 27.33,66.65 27.41,66.57 28.19,66.57 28.32,66.45 28.32,66.23 28.19,66.1 27.44,66.1 27.33,65.99 27.33,65.75 27.44,65.64 27.98,65.64 28.12,65.51 28.12,65.33 27.98,65.2 27.46,65.2 27.33,65.06 27.33,64.87 27.46,64.74 27.98,64.74 28.12,64.61 28.12,64.38 27.99,64.25 27.43,64.25 27.33,64.15 27.33,63.9 27.43,63.79 27.94,63.79 28.07,63.67 28.07,63.46 27.94,63.34 27.46,63.34 27.33,63.21 27.33,63.01 27.46,62.88 27.94,62.88 28.07,62.75 28.07,62.6 27.91,62.44 27.49,62.44 27.36,62.31 27.36,62.12 27.49,61.99 27.91,61.99 28.07,61.83 28.07,61.31 27.94,61.18 27.51,61.18 27.38,61.05 27.38,60.85 27.51,60.72 27.94,60.72 28.07,60.6 28.07,60.39 27.94,60.27 26.75,60.27 26.62,60.14 26.62,59.94 26.75,59.81 27.94,59.81 28.07,59.68 28.07,58.32 27.97,58.22 26.7,58.22 26.55,58.07 26.55,57.52 26.68,57.39 27.09,57.39 27.23,57.25 27.23,57.06 27.09,56.93 26.76,56.93 26.63,56.8 26.63,50.86 v2(26.3,50.54)
  ART06 w0.076: v1(22.61,46.23) 25.32,48.95 25.32,49.96 25.53,50.16 25.93,50.16 v2(26.3,50.54)
  BOTTOM w0.076: R255.2 v1(22.61,46.23)
LP3_CA7: length 48.8
  TOP w0.076: U5.E2 26.3,49.66 v2(26.3,49.74) ; R257.2 v1(23.75,46.23) ; U1.N20 v2(27.28,73.51)
  ART03 w0.076: v2(27.28,73.51) 27.29,73.5 27.29,71.1 27,70.82 27,70.69 27.13,70.56 27.99,70.56 28.12,70.43 28.12,70.23 27.99,70.1 27.13,70.1 27,69.98 27,69.77 27.13,69.65 27.94,69.65 28.07,69.52 28.07,69.32 27.94,69.19 27.13,69.19 27,69.06 27,68.86 27.13,68.73 27.94,68.73 28.07,68.61 28.07,68.4 27.94,68.28 27.13,68.28 27,68.15 27,67.94 27.13,67.82 27.99,67.82 28.12,67.69 28.12,67.49 27.99,67.36 27.13,67.36 27,67.23 27,61.63 26.85,61.48 25.15,61.48 25.02,61.35 25.02,61.15 25.15,61.02 26.92,61.02 27.05,60.9 27.05,60.69 26.92,60.57 25.15,60.57 25.02,60.44 25.02,60.24 25.15,60.11 26.21,60.11 26.29,60.03 26.29,59.5 26.45,59.34 27.52,59.34 27.64,59.23 27.64,58.99 27.53,58.89 26.09,58.89 25.98,58.77 25.98,58.51 26.16,58.32 26.16,58.06 25.98,57.88 25.98,50.06 v2(26.3,49.74)
  ART06 w0.076: v1(23.75,46.23) 23.75,46.89 26.3,49.44 v2(26.3,49.74)
  BOTTOM w0.076: R257.2 v1(23.75,46.23)
LP3_CA8: length 50.5
  TOP w0.076: U5.D2 25,49.66 v2(25,49.74) ; R259.2 v1(21.46,46.23) ; U1.M18 v2(27.28,75.46)
  ART03 w0.076: v2(25,49.74) 25.2,49.74 25.33,49.86 25.33,57.28 25.25,57.35 24.82,57.35 24.68,57.49 24.68,59 24.81,59.14 25.82,59.14 25.96,59.27 25.96,59.46 25.82,59.6 24.81,59.6 24.68,59.73 24.68,62 24.75,62.07 26.54,62.07 26.67,62.2 26.67,62.44 26.54,62.56 24.82,62.56 24.69,62.69 24.69,62.89 24.82,63.02 26.54,63.02 26.67,63.15 26.67,63.35 26.54,63.48 24.82,63.48 24.69,63.6 24.69,63.81 24.82,63.93 26.54,63.93 26.67,64.06 26.67,64.26 26.54,64.39 24.82,64.39 24.69,64.52 24.69,64.72 24.82,64.85 26.54,64.85 26.67,64.98 26.67,65.13 26.42,65.38 26.42,65.58 26.67,65.84 26.67,71.07 26.95,71.35 26.95,75.14 v2(27.28,75.46)
  ART06 w0.076: v2(25,49.74) 25,49.13 24.38,48.51 23.75,48.51 v1(21.46,46.23)
  BOTTOM w0.076: R259.2 v1(21.46,46.23)
LP3_CA9: length 48.9
  TOP w0.076: R261.2 v1(20.32,46.23) ; v2(24.35,49.74) 24.35,49.66 U5.C2 ; U1.P19 v2(26.63,74.16)
  ART03 w0.076: v2(26.63,74.16) 26.3,73.84 26.3,69.16 26.17,69.03 24.49,69.03 24.36,68.9 24.36,68.71 24.49,68.57 26.17,68.57 26.3,68.44 26.3,68.18 26.16,68.04 24.5,68.04 24.37,67.92 24.37,67.71 24.5,67.59 26.16,67.59 26.29,67.46 26.29,67.25 26.16,67.13 24.5,67.13 24.37,67 24.37,66.8 24.5,66.67 26.16,66.67 26.29,66.54 26.29,66.34 26.16,66.21 24.5,66.21 24.37,66.09 24.37,65.88 24.5,65.76 25.96,65.76 26.09,65.63 26.09,65.43 25.96,65.3 24.53,65.3 24.35,65.11 24.35,57.09 24.68,56.76 24.68,50.06 v2(24.35,49.74)
  ART06 w0.076: v2(24.35,49.74) 24.01,49.4 23.5,49.4 v1(20.32,46.23)
  BOTTOM w0.076: R261.2 v1(20.32,46.23)
LP3_CKE0: length 52.3
  TOP w0.076: R78.2 v1(26.04,46.23) ; v2(28.9,51.34) 28.9,50.83 29.22,50.51 U5.K3 ; U1.N17 v2(26.63,76.11)
  ART03 w0.076: v2(26.63,76.11) 26.95,76.44 28.09,76.44 28.25,76.27 28.25,72.21 29.21,71.25 29.21,69.6 30,68.81 30,68.62 29.91,68.53 29.91,68.34 30.04,68.21 30.23,68.21 30.32,68.3 30.51,68.3 30.86,67.94 30.86,63.52 30.73,63.39 28.93,63.39 28.8,63.26 28.8,61.8 28.91,61.7 29.31,61.7 29.41,61.8 29.41,62.76 29.54,62.88 29.76,62.88 29.89,62.75 29.89,62.36 30.03,62.23 30.22,62.23 30.35,62.36 30.35,62.75 30.49,62.88 30.73,62.88 30.86,62.76 30.86,61.32 30.78,61.24 28.98,61.24 28.83,61.09 28.83,60.89 28.96,60.76 30.81,60.76 30.91,60.66 30.91,60.38 30.84,60.31 28.96,60.31 28.83,60.18 28.83,55.98 28.57,55.73 28.57,51.46 28.7,51.34 v2(28.9,51.34)
  ART06 w0.076: v2(28.9,51.34) 28.51,50.95 27.38,50.95 27.27,50.84 27.27,48.68 26.57,47.98 26.57,46.76 v1(26.04,46.23)
  BOTTOM w0.076: R78.2 v1(26.04,46.23)
LP3_CLK_C: length 47.1
  TOP w0.089: v2(28.25,48.94) 28.25,49.01 U5.J2 ; U1.R20 v2(25.98,73.51)
  ART03 w0.089: v2(25.98,73.51) 25.98,73.73 25.89,73.82 25.73,73.82 25.49,73.58 25.49,73.26 25.28,73.06 25.28,72.91 25.41,72.78 25.41,72.63 25.31,72.53 25.16,72.53 25.03,72.66 24.88,72.66 24.78,72.55 24.78,72.41 24.93,72.25 24.93,72.1 24.83,72 24.68,72 24.53,72.15 24.38,72.15 23.33,71.1 23.33,59.07 22.97,58.71 21.58,58.71 21.42,58.55 21.42,58.33 21.58,58.17 22.97,58.17 23.33,57.82 23.33,53.2 22.68,52.55 22.68,50.98 23.11,50.55 23.11,49.91 22.68,49.48 22.68,49.07 23.5,48.26 24.51,48.26 24.89,48.64 25.78,48.64 26.16,48.26 26.95,48.26 27.05,48.36 27.05,48.54 27.15,48.64 27.3,48.64 27.41,48.54 27.41,48.36 27.51,48.26 27.66,48.26 27.76,48.36 27.76,48.54 27.87,48.64 28.01,48.64 28.12,48.54 28.12,48.36 28.22,48.26 28.4,48.26 28.74,48.6 28.74,49.06 28.65,49.15 28.46,49.15 v2(28.25,48.94)
  ART06 w0.089: v3(28.51,46.1) 28.74,46.33 28.74,49.06 28.65,49.15 28.46,49.15 v2(28.25,48.94)
  BOTTOM w0.089: R73.2 R72.2 28.73,45.62 28.73,45.89 v3(28.51,46.1)
LP3_CLK_T: length 47.6
  TOP w0.089: U5.J3 28.25,49.81 v2(28.25,49.74) ; U1.R19 v2(25.98,74.16)
  ART03 w0.089: v2(25.98,74.16) 25.59,74.16 25.15,73.72 25.15,73.41 22.99,71.25 22.99,59.21 22.83,59.05 21.44,59.05 21.08,58.69 21.08,58.19 21.44,57.83 22.83,57.83 22.99,57.68 22.99,53.34 22.34,52.69 22.34,50.84 22.77,50.4 22.77,50.05 22.34,49.62 22.34,48.93 23.35,47.92 24.65,47.92 25.03,48.3 25.64,48.3 26.02,47.92 28.54,47.92 29.08,48.46 29.08,49.2 28.79,49.49 28.5,49.49 v2(28.25,49.74)
  ART06 w0.089: v2(28.25,49.74) 28.5,49.49 28.79,49.49 29.08,49.2 29.08,46.29 v3(29.27,46.1)
  BOTTOM w0.089: v3(29.27,46.1) 29.02,45.85 29.02,45.66 R71.2 R70.2
